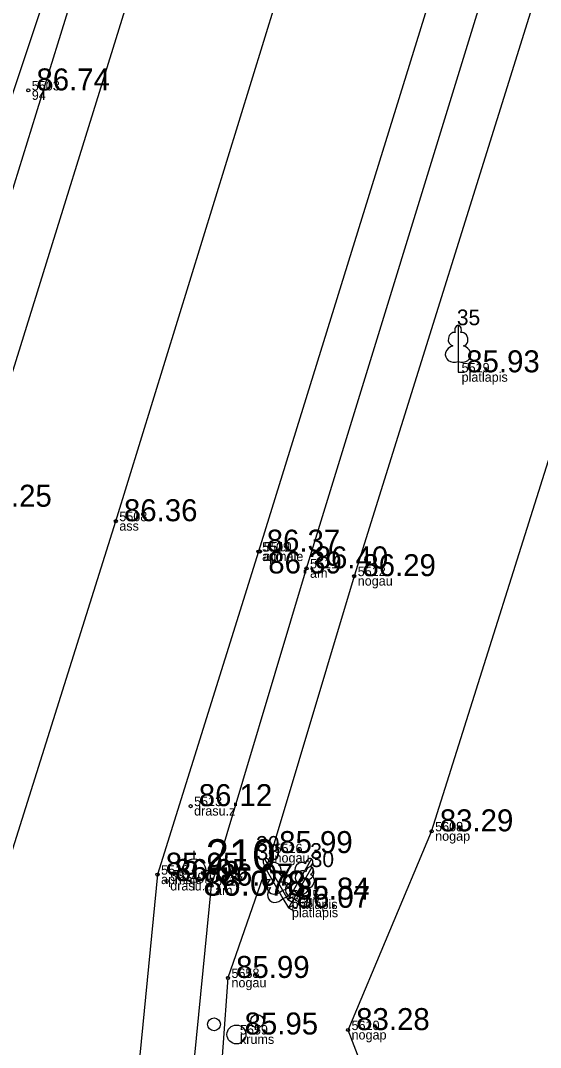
# Model space of a CAD drawing. Extents: x 614911 to 615803, y 262110 to 264311.
# Drawn here: x 615575.44 to 615592.01, y 262843.34 to 262876.06 of the extents above; entities that cross this region are included whole.
import ezdxf

# ---------------------------------------------------------------- set-up
doc = ezdxf.new("R2010")
doc.units = 0
for name, color, linetype in [('Level 1', 7, 'Continuous'), ('Level 19', 7, 'Continuous'), ('Level 31', 7, 'Continuous'), ('Level 37', 7, 'Continuous'), ('Level 53', 7, 'Continuous'), ('Level 54', 7, 'Continuous'), ('Level 57', 7, 'Continuous'), ('Level 58', 7, 'Continuous')]:
    doc.layers.add(name, color=color, linetype=linetype)

msp = doc.modelspace()

# ---------------------------------------------------------------- linework, layer by layer
at = {"layer": 'Level 1'}
for p, q in [((615589.381, 262865.196), (615589.381, 262864.849)), ((615589.381, 262864.849), (615589.581, 262864.849)), ((615583.786, 262848.352), (615583.959, 262848.051)), ((615584.132, 262848.352), (615583.959, 262848.051)), ((615583.801, 262848.089), (615583.974, 262847.788)), ((615583.959, 262848.051), (615584.132, 262848.151)), ((615583.959, 262848.051), (615584.132, 262847.951)), ((615584.147, 262848.089), (615583.974, 262847.788)), ((615583.974, 262847.788), (615584.147, 262847.888)), ((615583.974, 262847.788), (615584.147, 262847.688))]:
    msp.add_line(p, q, dxfattribs=at)
for points in [[(615589.381, 262866.349), (615589.381, 262865.196)], [(615589.471, 262866.117), (615589.47, 262866.118)], [(615583.209, 262849.35), (615583.786, 262848.352)], [(615584.709, 262849.35), (615584.132, 262848.352)], [(615583.224, 262849.087), (615583.801, 262848.089)], [(615583.403, 262849.194), (615583.401, 262849.194)], [(615583.418, 262848.931), (615583.416, 262848.931)], [(615584.724, 262849.087), (615584.147, 262848.089)], [(615584.67, 262849.104), (615584.67, 262849.105)], [(615584.685, 262848.841), (615584.685, 262848.842)]]:
    msp.add_lwpolyline(points, dxfattribs=at)
for centre, radius in [((615582.979, 262844.178), 0.207), ((615581.604, 262844.077), 0.204), ((615582.318, 262843.753), 0.301)]:
    msp.add_circle(centre, radius, dxfattribs=at)
for centre, major_axis, ratio, start_param, end_param in [((615589.381, 262866.199), (0, -0.15), 0.707107, 3.14537, 5.287485), ((615589.381, 262866.199), (0, -0.15), 0.707107, 0.995701, 3.137816), ((615589.253, 262865.904), (-0.039, -0.212), 0.861323, 3.141593, 6.283185), ((615589.509, 262865.904), (0.039, -0.212), 0.861323, 0, 3.141593), ((615589.291, 262865.442), (0.307, 0.095), 0.814445, 1.570796, 4.752015), ((615589.471, 262865.442), (-0.307, 0.095), 0.814445, 1.531171, 4.712389), ((615583.284, 262849.22), (0.075, -0.13), 0.707107, 3.14537, 5.287485), ((615583.284, 262849.22), (0.075, -0.13), 0.707107, 0.995701, 3.137816), ((615583.543, 262849.029), (0.14, -0.165), 0.861323, 0, 3.141593), ((615584.375, 262849.029), (-0.14, -0.165), 0.861323, 3.141593, 6.283185), ((615584.634, 262849.22), (-0.075, -0.13), 0.707107, 3.14537, 5.287485), ((615584.634, 262849.22), (-0.075, -0.13), 0.707107, 0.995701, 3.137816), ((615583.32, 262848.901), (0.073, -0.203), 0.861323, 3.141593, 6.283185), ((615583.299, 262848.957), (0.075, -0.13), 0.707107, 3.14537, 5.287485), ((615583.299, 262848.957), (0.075, -0.13), 0.707107, 0.995701, 3.137816), ((615583.558, 262848.766), (0.14, -0.165), 0.861323, 0, 3.141593), ((615583.74, 262848.609), (-0.313, -0.071), 0.814445, 1.531171, 4.712389), ((615584.178, 262848.609), (0.313, -0.071), 0.814445, 1.570796, 4.752015), ((615584.39, 262848.766), (-0.14, -0.165), 0.861323, 3.141593, 6.283185), ((615584.598, 262848.901), (-0.073, -0.203), 0.861323, 0, 3.141593), ((615584.649, 262848.957), (-0.075, -0.13), 0.707107, 3.14537, 5.287485), ((615584.649, 262848.957), (-0.075, -0.13), 0.707107, 0.995701, 3.137816), ((615583.335, 262848.638), (0.073, -0.203), 0.861323, 3.141593, 6.283185), ((615583.585, 262848.52), (0.218, 0.236), 0.814445, 1.570796, 4.752015), ((615583.755, 262848.346), (-0.313, -0.071), 0.814445, 1.531171, 4.712389), ((615584.193, 262848.346), (0.313, -0.071), 0.814445, 1.570796, 4.752015), ((615584.333, 262848.52), (-0.218, 0.236), 0.814445, 1.531171, 4.712389), ((615584.613, 262848.638), (-0.073, -0.203), 0.861323, 0, 3.141593), ((615583.6, 262848.257), (0.218, 0.236), 0.814445, 1.570796, 4.752015), ((615584.348, 262848.257), (-0.218, 0.236), 0.814445, 1.531171, 4.712389)]:
    msp.add_ellipse(centre, major_axis=major_axis, ratio=ratio, start_param=start_param, end_param=end_param, dxfattribs=at)
at = {"layer": 'Level 19'}
for p, q in [((615580.966, 262849.349), (615580.966, 262849.599)), ((615580.341, 262848.974), (615580.591, 262848.974)), ((615581.341, 262848.974), (615581.591, 262848.974)), ((615580.966, 262848.349), (615580.966, 262848.599))]:
    msp.add_line(p, q, dxfattribs=at)
for radius in [0.375, 0.05]:
    msp.add_circle((615580.966, 262848.974), radius, dxfattribs=at)
at = {"layer": 'Level 31'}
for points in [[(615630.111, 263159.019), (615628.675, 263155.243), (615625.969, 263148.507), (615625.467, 263143.326), (615625.424, 263137.065), (615625.842, 263134.993), (615625.948, 263131.109), (615625.2, 263127.266), (615625.864, 263116.003), (615625.339, 263108.896), (615618.12, 263017.928), (615614.008, 263002.211), (615611.608, 262992.724), (615610.318, 262984.066), (615604.711, 262969.009), (615598.026, 262946.805), (615590.694, 262924.523), (615584.099, 262903.018), (615578.016, 262882.248), (615571.57, 262862.909), (615571.479, 262861.254), (615568.795, 262854.862), (615562.238, 262831.156), (615556.487, 262814.508)], [(615632.734, 262974.874), (615627.762, 262975.783), (615624.583, 262974.081), (615622.329, 262970.726), (615619.288, 262963.641), (615611.976, 262941.852), (615605.37, 262920.098), (615598.524, 262898.844), (615592.115, 262877.692), (615586.071, 262858.355), (615583.42, 262849.533), (615582.048, 262845.554), (615581.571, 262838.931), (615579.909, 262826.022), (615579.783, 262825.588), (615576.605, 262812.081)], [(615581.33, 262813.385), (615587.235, 262840.341), (615585.874, 262843.893), (615588.538, 262850.225), (615593.068, 262864.597), (615600.932, 262884.287), (615612.047, 262917.578), (615615.98, 262929.024), (615621.827, 262931.099), (615623.831, 262935.169), (615622.903, 262940.536), (615628.682, 262961.888), (615634.511, 262966.199), (615634.511, 262966.199)]]:
    msp.add_lwpolyline(points, dxfattribs=at)
at = {"layer": 'Level 37'}
for points in [[(615629.654, 263149.948), (615628.721, 263134.164), (615628.583, 263132.388), (615627.854, 263104.61), (615621.91, 263025.585), (615621.904, 263025.311), (615619.521, 263012.239), (615619.398, 263011.725), (615613.627, 262992.503), (615605.986, 262968.61), (615598.735, 262946.405), (615591.778, 262924.107), (615585.103, 262902.604), (615578.685, 262882.008), (615572.188, 262861.032), (615562.921, 262830.982), (615557.662, 262813.841), (615551.445, 262793.883), (615545.378, 262774.577), (615544.847, 262773.643)], [(615552.83, 262775.419), (615557.688, 262792.217), (615564.381, 262810.929), (615568.874, 262829.598), (615578.474, 262860.105), (615584.765, 262880.506), (615591.133, 262901.009), (615597.793, 262922.52), (615604.506, 262944.221), (615611.821, 262967.016), (615619.311, 262990.31), (615624.144, 263005.661), (615628.856, 263023.992)], [(615633.153, 262995.478), (615630.105, 262994.778), (615627.249, 262993.097), (615624.165, 262989.775), (615623.012, 262986.721), (615615.941, 262964.659), (615608.941, 262942.572), (615602.23, 262921.018), (615595.493, 262899.514), (615589.041, 262878.574), (615583.023, 262859.136), (615579.804, 262848.845), (615577.579, 262826.156), (615572.51, 262808.384), (615566.84, 262788.492), (615562.353, 262772.755), (615562.228, 262772.268), (615562.322, 262770.686), (615563.546, 262768.507), (615565.703, 262767.319), (615569.868, 262766.432), (615584.992, 262762.796)], [(615615.254, 262992.037), (615607.495, 262968.204), (615600.361, 262945.823), (615593.41, 262923.721), (615586.741, 262902.064), (615580.351, 262881.537), (615573.832, 262860.567), (615564.576, 262830.529), (615559.267, 262813.314), (615553.068, 262793.425), (615547.108, 262774.302), (615545.744, 262772.518), (615544.641, 262771.987), (615542.393, 262772.794), (615538.581, 262772.6), (615523.132, 262777.208), (615510.602, 262781.905), (615510.241, 262783.659)], [(615576.19, 262811.993), (615576.066, 262812.682), (615575.818, 262813.59), (615579.291, 262825.832), (615581.523, 262848.494), (615584.551, 262858.603), (615590.575, 262878.181), (615597.215, 262899.18), (615604.023, 262920.582), (615610.418, 262942.235), (615617.538, 262964.274), (615623.159, 262980.563)]]:
    msp.add_lwpolyline(points, dxfattribs=at)
at = {"layer": 'Level 57'}
for centre in [(615575.685, 262873.83), (615578.474, 262860.105), (615583.023, 262859.136), (615583.072, 262859.141), (615584.551, 262858.603), (615586.071, 262858.355), (615580.857, 262851.028), (615588.538, 262850.225), (615588.539, 262850.225), (615583.42, 262849.533), (615579.804, 262848.845), (615580.096, 262848.642), (615581.523, 262848.494), (615582.048, 262845.554), (615585.874, 262843.893)]:
    msp.add_circle(centre, 0.05, dxfattribs=at)
at = {"layer": 'Level 58'}
for centre in [(615575.685, 262873.83), (615578.474, 262860.105), (615583.023, 262859.136), (615583.072, 262859.141), (615584.551, 262858.603), (615586.071, 262858.355), (615580.857, 262851.028), (615588.538, 262850.225), (615588.539, 262850.225), (615583.42, 262849.533), (615579.804, 262848.845), (615580.096, 262848.642), (615581.523, 262848.494), (615582.048, 262845.554), (615585.874, 262843.893)]:
    msp.add_circle(centre, 0.05, dxfattribs=at)

# ---------------------------------------------------------------- texts
at = {"layer": 'Level 1'}
for s, p in [(' 35', (615589.156, 262866.349)), (' 30', (615582.759, 262849.575)), (' 30', (615582.774, 262849.312)), (' 3', (615584.484, 262849.35)), (' 30', (615584.499, 262849.087))]:
    msp.add_text(s, height=0.5, dxfattribs=at).set_placement(p)
at = {"layer": 'Level 19'}
for s, height, p in [(' 210', 1, (615580.966, 262848.974)), (' 86.078', 0.8, (615580.966, 262848.174))]:
    msp.add_text(s, height=height, dxfattribs=at).set_placement(p)
at = {"layer": 'Level 53'}
for s, p in [(' 94', (615575.685, 262873.53)), (' platlapis', (615589.381, 262864.549)), (' ass', (615578.474, 262859.805)), (' apmale', (615583.023, 262858.836)), (' ap', (615583.072, 262858.841)), (' am', (615584.551, 262858.303)), (' nogau', (615586.071, 262858.055)), (' drasu.z', (615580.857, 262850.728)), (' nogap', (615588.538, 262849.925)), (' nogap', (615588.539, 262849.925)), (' nogau', (615583.42, 262849.233)), (' gp', (615580.966, 262848.674)), (' apmale', (615579.804, 262848.545)), (' drasu.z', (615580.096, 262848.342)), (' am', (615581.523, 262848.194)), (' platlapis', (615583.959, 262847.751)), (' platlapis', (615583.974, 262847.488)), (' nogau', (615582.048, 262845.254)), (' krums', (615582.318, 262843.453)), (' nogap', (615585.874, 262843.593))]:
    msp.add_text(s, height=0.3, dxfattribs=at).set_placement(p)
at = {"layer": 'Level 54'}
for s, p in [(' 5503', (615575.685, 262873.83)), (' 5519', (615589.381, 262864.849)), (' 5508', (615578.474, 262860.105)), (' 5509', (615583.023, 262859.136)), (' 5510', (615583.072, 262859.141)), (' 5511', (615584.551, 262858.603)), (' 5512', (615586.071, 262858.355)), (' 5513', (615580.857, 262851.028)), (' 5608', (615588.538, 262850.225)), (' 5609', (615588.539, 262850.225)), (' 5516', (615583.42, 262849.533)), (' 5518', (615579.804, 262848.845)), (' 5514', (615580.096, 262848.642)), (' 5517', (615581.523, 262848.494)), (' 5515', (615583.959, 262848.051)), (' 5657', (615583.974, 262847.788)), (' 5658', (615582.048, 262845.554)), (' 5659', (615582.318, 262843.753)), (' 5610', (615585.874, 262843.893))]:
    msp.add_text(s, height=0.3, dxfattribs=at).set_placement(p)
at = {"layer": 'Level 58'}
for s, p in [(' 86.74', (615575.685, 262873.83)), (' 85.93', (615589.381, 262864.849)), (' 86.25', (615573.832, 262860.567)), (' 86.36', (615578.474, 262860.105)), (' 86.37', (615583.023, 262859.136)), (' 86.39', (615583.072, 262858.441)), (' 86.40', (615584.551, 262858.603)), (' 86.29', (615586.071, 262858.355)), (' 86.12', (615580.857, 262851.028)), (' 83.29', (615588.538, 262850.225)), (' 83.29', (615588.539, 262850.225)), (' 85.99', (615583.42, 262849.533)), (' 85.95', (615579.804, 262848.845)), (' 86.05', (615580.096, 262848.642)), (' 86.07', (615581.523, 262848.494)), (' 85.84', (615583.959, 262848.051)), (' 86.07', (615583.974, 262847.788)), (' 85.99', (615582.048, 262845.554)), (' 85.95', (615582.318, 262843.753)), (' 83.28', (615585.874, 262843.893))]:
    msp.add_text(s, height=0.7, dxfattribs=at).set_placement(p)

doc.saveas('drawing.dxf')
